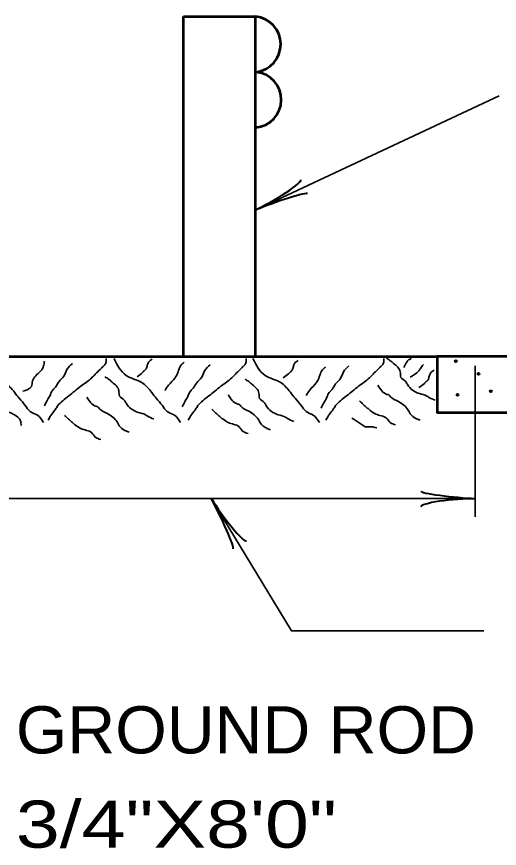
# Model space of a CAD drawing. Extents: x 12366 to 13046, y 9129 to 9570.
# Drawn here: x 12473.04 to 12498.62, y 9368.08 to 9412.18 of the extents above; entities that cross this region are included whole.
import ezdxf

# ---------------------------------------------------------------- set-up
doc = ezdxf.new("R2010")
doc.units = 0
doc.layers.add('1', color=7, linetype='Continuous', lineweight=53)

msp = doc.modelspace()

# ---------------------------------------------------------------- linework, layer by layer
at = {"layer": '1'}
for p, q in [((12481.882, 9394.167), (12481.882, 9412.184)), ((12481.882, 9412.184), (12485.704, 9412.184)), ((12485.704, 9394.167), (12485.704, 9412.184)), ((12469.382, 9394.167), (12495.321, 9394.167))]:
    msp.add_line(p, q, dxfattribs=at)
at = {"layer": '1', "lineweight": 35}
for p, q in [((12485.686, 9401.927), (12498.607, 9407.985)), ((12497.328, 9393.668), (12497.328, 9385.668)), ((12497.328, 9386.63), (12469.382, 9386.63))]:
    msp.add_line(p, q, dxfattribs=at)
at = {"layer": '1'}
for points in [[(12495.321, 9394.186), (12620.321, 9394.186), (12620.321, 9397.186), (12649.358, 9397.186)], [(12495.321, 9394.167), (12495.321, 9391.186), (12622.571, 9391.186), (12622.571, 9397.186)]]:
    msp.add_lwpolyline(points, dxfattribs=at)
at = {"layer": '1', "lineweight": 35}
msp.add_lwpolyline([(12483.355, 9386.63), (12487.604, 9379.611), (12497.799, 9379.611)], dxfattribs=at)
at = {"layer": '1', "lineweight": 40}
for centre in [(12496.31, 9393.914), (12497.518, 9393.243), (12496.407, 9392.132), (12498.171, 9392.317)]:
    msp.add_circle(centre, 0.05, dxfattribs=at)
at = {"layer": '1'}
for centre, start in [((12485.553, 9410.714), 277.1257), ((12485.586, 9407.777), 274.5392)]:
    msp.add_arc(centre, 1.478, start, 84.1489, dxfattribs=at)
at = {"layer": '1', "lineweight": 40}
for centre, major_axis, ratio, start_param, end_param in [((12486.557, 9402.64), (-1.55, -0.899), 0.122415, 0.896353, 3.141593), ((12486.791, 9402.211), (-1.665, -0.587), 0.07063, 3.140715, 5.41811), ((12496.207, 9386.842), (1.756, -0.176), 0.07063, 3.140715, 5.41811), ((12483.754, 9385.562), (-0.759, 1.594), 0.07063, 3.140715, 5.41811), ((12484.156, 9385.84), (-1.058, 1.447), 0.122415, 0.896353, 3.141593), ((12496.237, 9386.354), (1.786, 0.156), 0.122415, 0.896353, 3.141593)]:
    msp.add_ellipse(centre, major_axis=major_axis, ratio=ratio, start_param=start_param, end_param=end_param, dxfattribs=at)
at = {"layer": '1', "lineweight": 35}
for points in [[(12470.942, 9394.056), (12471.582, 9393.161), (12472.413, 9392.777), (12472.925, 9392.265), (12473.181, 9391.945), (12473.501, 9391.561), (12473.757, 9391.242), (12474.141, 9391.05), (12474.46, 9390.666)], [(12473.373, 9392.321), (12473.821, 9392.577), (12473.885, 9392.865), (12474.3, 9393.377), (12474.428, 9393.537), (12474.492, 9393.793), (12474.524, 9393.921)], [(12477.787, 9394.056), (12477.787, 9393.929), (12477.723, 9393.737), (12477.595, 9393.609), (12477.467, 9393.481), (12477.211, 9393.225), (12477.02, 9393.033), (12476.444, 9392.585), (12476.124, 9392.329), (12475.484, 9391.817), (12475.228, 9391.561), (12475.1, 9391.369), (12474.908, 9391.113), (12474.716, 9390.794)], [(12478.203, 9394.056), (12478.843, 9393.161), (12479.675, 9392.777), (12480.187, 9392.265), (12480.442, 9391.945), (12480.762, 9391.561), (12481.018, 9391.242), (12481.402, 9391.05), (12481.722, 9390.666)], [(12480.218, 9394.017), (12480.026, 9393.857), (12479.962, 9393.697), (12479.898, 9393.505), (12479.771, 9393.377), (12479.707, 9393.313), (12479.419, 9393.089)], [(12485.209, 9394.056), (12485.209, 9393.929), (12485.145, 9393.737), (12485.017, 9393.609), (12484.889, 9393.481), (12484.633, 9393.225), (12484.441, 9393.033), (12483.865, 9392.585), (12483.545, 9392.329), (12482.906, 9391.817), (12482.65, 9391.561), (12482.522, 9391.369), (12482.33, 9391.113), (12482.138, 9390.794)], [(12485.561, 9394.056), (12486.201, 9393.161), (12487.032, 9392.777), (12487.544, 9392.265), (12487.8, 9391.945), (12488.12, 9391.561), (12488.376, 9391.242), (12488.76, 9391.05), (12489.08, 9390.666)], [(12487.96, 9393.953), (12487.768, 9393.793), (12487.704, 9393.633), (12487.64, 9393.441), (12487.512, 9393.313), (12487.448, 9393.249), (12487.16, 9393.025)], [(12492.502, 9394.056), (12492.502, 9393.929), (12492.438, 9393.737), (12492.31, 9393.609), (12492.182, 9393.481), (12491.926, 9393.225), (12491.735, 9393.033), (12491.159, 9392.585), (12490.839, 9392.329), (12490.199, 9391.817), (12489.943, 9391.561), (12489.815, 9391.369), (12489.623, 9391.113), (12489.431, 9390.794)], [(12492.63, 9394.081), (12492.822, 9393.953), (12493.014, 9393.793), (12493.366, 9393.345), (12493.398, 9393.057), (12493.654, 9392.833), (12493.75, 9392.673), (12494.39, 9392.193), (12494.774, 9392.065), (12494.87, 9392.001), (12495.221, 9391.842)], [(12493.947, 9394.127), (12493.851, 9393.999), (12493.819, 9393.999), (12493.755, 9393.935), (12493.595, 9393.647), (12493.563, 9393.583)], [(12475.996, 9393.793), (12475.708, 9393.473), (12475.548, 9393.121), (12475.292, 9392.833), (12475.1, 9392.545), (12474.908, 9392.321), (12474.812, 9392.097), (12474.684, 9391.873), (12474.524, 9391.554)], [(12481.914, 9393.857), (12481.722, 9393.665), (12481.594, 9393.345), (12481.434, 9393.025), (12481.082, 9392.641), (12480.954, 9392.449), (12480.89, 9392.353)], [(12483.289, 9393.729), (12483.002, 9393.409), (12482.842, 9393.057), (12482.586, 9392.769), (12482.394, 9392.481), (12482.202, 9392.257), (12482.106, 9392.033), (12481.978, 9391.809), (12481.818, 9391.49)], [(12489.399, 9393.601), (12489.208, 9393.409), (12489.079, 9393.089), (12488.92, 9392.769), (12488.568, 9392.386), (12488.44, 9392.193), (12488.376, 9392.098)], [(12490.647, 9393.665), (12490.359, 9393.345), (12490.199, 9392.993), (12489.943, 9392.705), (12489.751, 9392.417), (12489.559, 9392.193), (12489.463, 9391.969), (12489.335, 9391.745), (12489.175, 9391.426)], [(12493.888, 9393.071), (12494.336, 9393.391), (12494.432, 9393.519), (12494.592, 9393.743)], [(12495.157, 9393.441), (12494.965, 9393.281), (12494.901, 9393.121), (12494.837, 9392.929), (12494.709, 9392.801), (12494.645, 9392.737), (12494.358, 9392.513)], [(12470.814, 9393.121), (12470.942, 9392.737), (12471.198, 9392.321), (12471.517, 9391.906), (12471.837, 9391.714), (12472.381, 9391.33), (12473.245, 9390.754), (12473.277, 9390.498)], [(12477.723, 9393.089), (12477.915, 9392.961), (12478.107, 9392.801), (12478.459, 9392.353), (12478.491, 9392.065), (12478.747, 9391.842), (12478.843, 9391.682), (12479.483, 9391.202), (12479.867, 9391.074), (12479.963, 9391.01), (12480.314, 9390.85)], [(12485.145, 9392.961), (12485.337, 9392.833), (12485.529, 9392.673), (12485.881, 9392.225), (12485.913, 9391.938), (12486.168, 9391.714), (12486.264, 9391.554), (12486.904, 9391.074), (12487.288, 9390.946), (12487.384, 9390.882), (12487.736, 9390.722)], [(12492.183, 9392.635), (12492.663, 9392.155), (12492.759, 9392.123), (12492.855, 9392.027), (12493.271, 9391.771), (12493.783, 9391.323), (12493.943, 9391.067), (12494.422, 9390.78)], [(12484.249, 9392.129), (12484.729, 9391.65), (12484.825, 9391.618), (12484.921, 9391.522), (12485.337, 9391.266), (12485.849, 9390.818), (12486.008, 9390.562), (12486.488, 9390.274)], [(12476.764, 9392.002), (12477.244, 9391.522), (12477.34, 9391.49), (12477.435, 9391.394), (12477.851, 9391.138), (12478.363, 9390.69), (12478.523, 9390.434), (12479.003, 9390.146)], [(12491.203, 9391.814), (12491.619, 9391.43), (12491.779, 9391.302), (12492.066, 9391.11), (12492.642, 9390.887), (12492.834, 9390.663), (12493.122, 9390.535)], [(12483.385, 9391.362), (12483.801, 9390.978), (12483.961, 9390.85), (12484.249, 9390.658), (12484.825, 9390.434), (12485.017, 9390.21), (12485.305, 9390.082)], [(12475.58, 9391.042), (12475.996, 9390.658), (12476.156, 9390.53), (12476.444, 9390.338), (12477.02, 9390.114), (12477.211, 9389.89), (12477.499, 9389.762)], [(12490.809, 9390.887), (12491.033, 9390.759), (12491.449, 9390.471), (12491.512, 9390.439), (12491.704, 9390.439), (12492.12, 9390.375)]]:
    msp.add_spline(points, degree=3, dxfattribs=at)

# ---------------------------------------------------------------- texts
at = {"layer": '1'}
for s, width, p in [('GROUND ROD', 1.05, (12473, 9373.117)), ('3/4"X8\'0"', 1.25, (12473, 9368.117))]:
    msp.add_text(s, height=2.5, dxfattribs=dict(at, width=width)).set_placement(p)

doc.saveas('drawing.dxf')
